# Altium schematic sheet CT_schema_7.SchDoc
size 308 x 210 mm
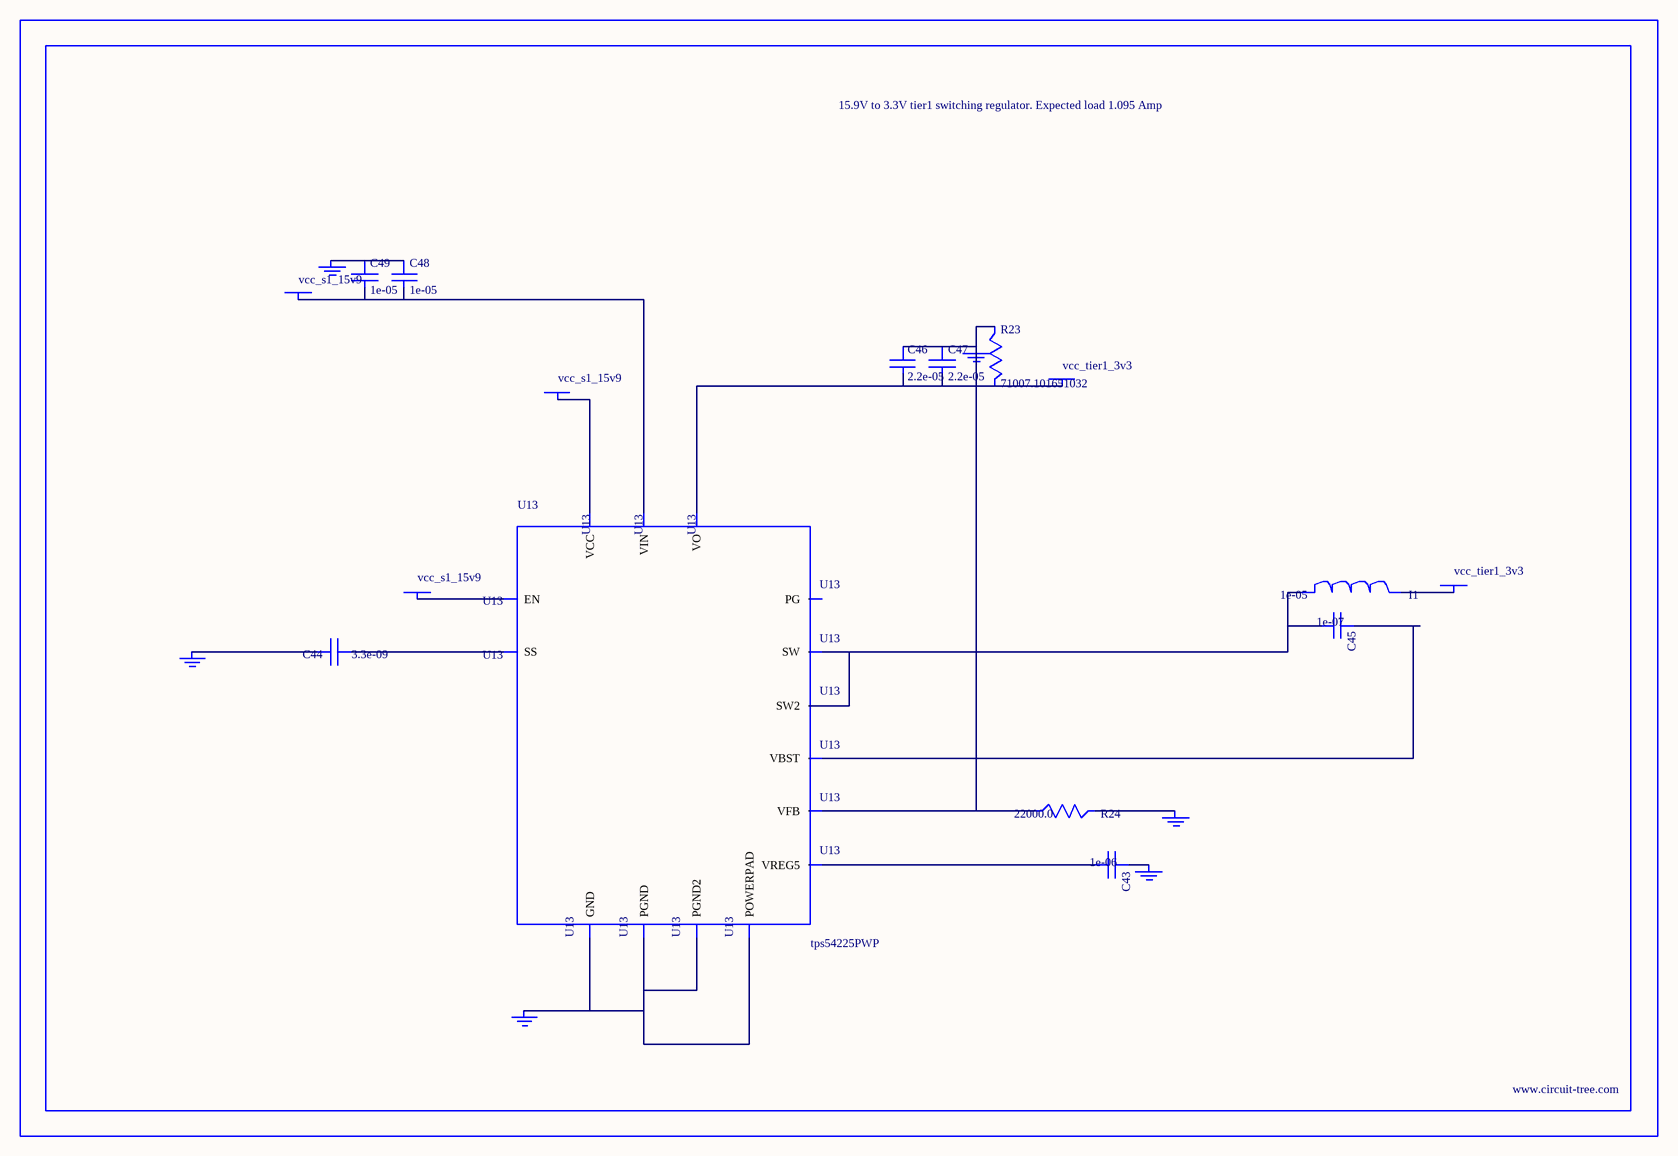
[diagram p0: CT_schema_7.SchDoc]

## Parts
BORDER6  (no value)
C43  1e-06  [C0603]
C44  3.3e-09  [C0402]
C45  1e-07  [C0402]
C46  2.2e-05  [C1210]
C47  2.2e-05  [C1210]
C48  1e-05  [C1206]
C49  1e-05  [C1206]
GND_INSTANCE_6_0  (no value)
GND_INSTANCE_6_1  (no value)
GND_INSTANCE_6_2  (no value)
GND_INSTANCE_6_3  (no value)
GND_INSTANCE_6_4  (no value)
GND_INSTANCE_6_5  (no value)
I1  1e-05  [IND_PM3316]
POWER_INSTANCE_6_0  vcc_tier1_3v3
POWER_INSTANCE_6_1  vcc_s1_15v9
POWER_INSTANCE_6_2  vcc_tier1_3v3
POWER_INSTANCE_6_3  vcc_s1_15v9
POWER_INSTANCE_6_4  vcc_s1_15v9
R23  71007.101651032  [R0603]
R24  22000.0  [R0603]
U13  tps54225PWP  [HTSSOP14]

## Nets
NetC43_1: C43.1 GND_INSTANCE_6_2.0(GND)
NetC43_2: C43.2 U13.3(VREG5)
NetC44_1: C44.1 U13.4(SS)
NetC44_2: C44.2 GND_INSTANCE_6_3.0(GND)
NetC45_1: C45.1 U13.12(VBST)
NetC45_2: C45.2 I1.1 U13.10(SW) U13.11(SW2)
NetC46_1: C46.1 C47.1 GND_INSTANCE_6_0.0(GND) R23.1 R24.1 U13.2(VFB)
NetC46_2: C46.2 C47.2 POWER_INSTANCE_6_0.0(PWR) R23.2 U13.1(VO)
NetC48_1: C48.1 C49.1 GND_INSTANCE_6_5.0(GND)
NetC48_2: C48.2 C49.2 POWER_INSTANCE_6_3.0(PWR) U13.13(VIN)
NetGND_INSTANCE_6_1_0: GND_INSTANCE_6_1.0(GND) R24.2
NetGND_INSTANCE_6_4_0: GND_INSTANCE_6_4.0(GND) U13.5(GND) U13.8(PGND) U13.9(PGND2) U13.15(POWERPAD)
NetI1_2: I1.2 POWER_INSTANCE_6_2.0(PWR)
NetPOWER_INSTANCE_6_1_0: POWER_INSTANCE_6_1.0(PWR) U13.7(EN)
NetPOWER_INSTANCE_6_4_0: POWER_INSTANCE_6_4.0(PWR) U13.14(VCC)

Not connected (* = marked no-connect by the designer): U13 6(PG)

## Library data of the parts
BORDER6 = BORDER_PAGE6
C43 = C0603C105K3RACTU
C44 = C0402C332K3RAC
C45 = C0402C104K3RACTU
C46 C47 = GRM32ER61E226ME15L
C48 C49 = C1206C106K3RACTU
GND_INSTANCE_6_0-GND_INSTANCE_6_5 = GND
I1 = PM3316-100M-RC
POWER_INSTANCE_6_0-POWER_INSTANCE_6_4 = PWR
R23 = R23
R24 = RC0603JR-0722KL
